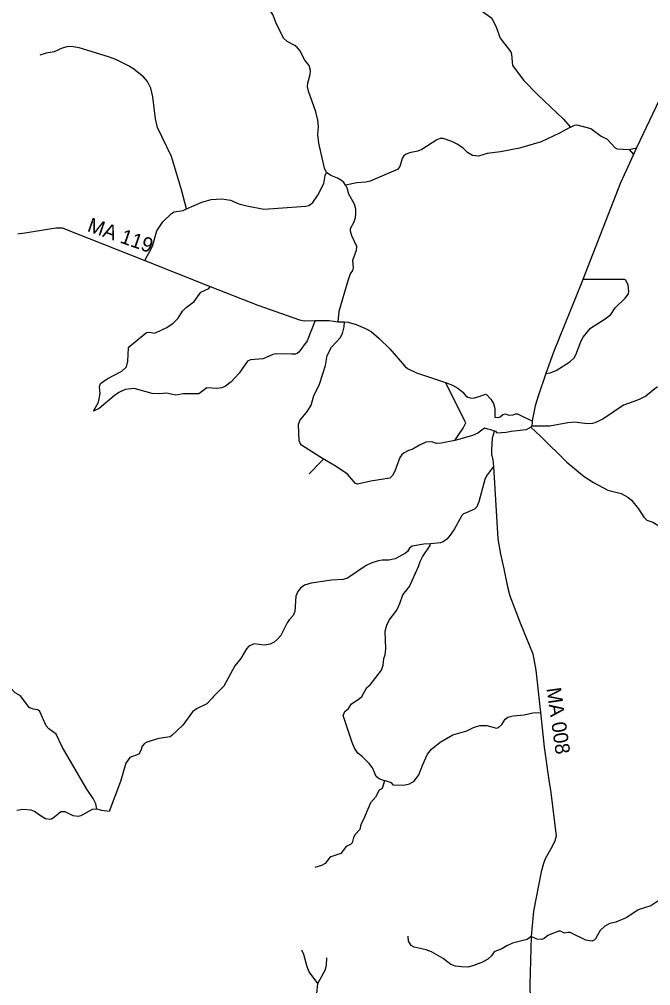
# Model space of a CAD drawing. Extents: x 332 to 501, y 9447 to 9559.
# Drawn here: x 460.06 to 476.49, y 9511.64 to 9536.78 of the extents above; entities that cross this region are included whole.
import ezdxf

# ---------------------------------------------------------------- set-up
doc = ezdxf.new("R2010")
doc.units = 0
for name, color, linetype in [('Level 2', 7, 'Continuous'), ('Level 31', 7, 'Continuous'), ('Level 4', 7, 'Continuous'), ('Level 5', 7, 'Continuous'), ('Level 6', 7, 'Continuous'), ('Level 7', 7, 'Continuous'), ('Level 8', 7, 'Continuous')]:
    doc.layers.add(name, color=color, linetype=linetype)

msp = doc.modelspace()

# ---------------------------------------------------------------- linework, layer by layer
at = {"layer": 'Level 2'}
for points in [[(476.9728, 9535.2227), (476.1217, 9533.4359)], [(476.0422, 9533.261), (475.8954, 9532.9401)], [(476.1217, 9533.4359), (476.0422, 9533.261)], [(475.8954, 9532.9401), (475.7029, 9532.5298), (474.7247, 9530.0083)], [(474.7247, 9530.0083), (474.6986, 9529.941)], [(474.6986, 9529.941), (473.9637, 9528.1206), (473.7625, 9527.5643)], [(473.7625, 9527.5643), (473.5586, 9526.9752), (473.4879, 9526.7279), (473.4094, 9526.3344)], [(473.404, 9526.3076), (473.3946, 9526.2002)], [(473.4094, 9526.3344), (473.404, 9526.3076)]]:
    msp.add_lwpolyline(points, dxfattribs=at)
at = {"layer": 'Level 4'}
for points in [[(460.0993, 9531.2058), (461.0047, 9531.3593), (461.1721, 9531.3548), (463.3279, 9530.5034)], [(463.3279, 9530.5034), (465.022, 9529.8323)], [(465.022, 9529.8323), (466.261, 9529.348), (467.3464, 9528.958), (467.4676, 9528.9403), (467.7569, 9528.9458)], [(467.7569, 9528.9458), (468.1214, 9528.9428), (468.3481, 9528.9107)], [(468.3481, 9528.9107), (468.5226, 9528.9082)], [(468.5226, 9528.9082), (468.6186, 9528.9025), (468.8206, 9528.8368), (469.0655, 9528.7397), (469.2146, 9528.6616), (469.4144, 9528.4872), (469.6996, 9528.2045), (470.0903, 9527.754), (470.1597, 9527.6971), (470.3983, 9527.5873), (471.1483, 9527.3317)], [(471.1483, 9527.3317), (471.3322, 9527.2655), (471.4748, 9527.1822), (471.6023, 9527.0787), (471.6729, 9526.9922), (471.7336, 9526.9525), (471.7891, 9526.931), (471.8711, 9526.9247), (472.0261, 9526.9672)], [(472.0261, 9526.9672), (472.1934, 9527.0257)], [(472.1934, 9527.0257), (472.2287, 9527.0118)], [(472.352, 9525.4304), (472.3861, 9525.318)], [(472.3861, 9525.318), (472.3965, 9525.148)], [(472.3965, 9525.148), (472.5111, 9523.267), (472.5818, 9522.8631), (472.6692, 9522.4887)], [(472.6692, 9522.4887), (472.7634, 9522.0149), (472.8253, 9521.7852), (473.0941, 9521.0785), (473.4223, 9520.2783), (473.498, 9519.8466), (473.627, 9518.7501)], [(473.627, 9518.7501), (473.6355, 9518.6673)], [(473.6355, 9518.6673), (473.7201, 9517.8423), (473.8439, 9516.9871)], [(473.8439, 9516.9871), (473.8941, 9516.6696)], [(473.8941, 9516.6696), (474.0307, 9515.5298)], [(474.0307, 9515.5298), (473.9965, 9515.4101), (473.9258, 9515.2612), (473.7461, 9514.9437), (473.6974, 9514.8233), (473.6419, 9514.6037), (473.4424, 9513.5839), (473.3815, 9512.9204)], [(473.3815, 9512.9204), (473.3415, 9511.6756), (473.3582, 9511.3032)]]:
    msp.add_lwpolyline(points, dxfattribs=at)
at = {"layer": 'Level 5'}
for points in [[(468.057, 9532.7962), (468.0014, 9532.9072), (467.8515, 9533.5612), (467.8286, 9533.7806), (467.8412, 9533.9927), (467.826, 9534.1593), (467.7793, 9534.3738), (467.5837, 9534.914), (467.561, 9535.0201), (467.5686, 9535.1286), (467.6253, 9535.3432), (467.6367, 9535.4492), (467.6026, 9535.5766), (467.4916, 9535.7205), (467.3565, 9535.9654), (467.2971, 9536.0389), (467.2267, 9536.0983), (467.0309, 9536.2039), (466.9324, 9536.2872), (466.7457, 9536.676), (466.6548, 9536.9032), (466.5828, 9537.0091), (466.4591, 9537.1177), (466.2565, 9537.2555)], [(471.9087, 9537.1788), (472.0856, 9536.9993), (472.3506, 9536.8195), (472.4629, 9536.6012), (472.5753, 9536.2907), (472.849, 9535.9297), (472.8693, 9535.8702), (472.8745, 9535.7654)], [(472.8745, 9535.7654), (472.8926, 9535.5787), (473.1914, 9535.1867), (473.5498, 9534.8181), (474.2149, 9534.1933), (474.4022, 9533.9722)], [(464.4074, 9531.8478), (464.2785, 9532.3419), (464.0169, 9533.2102), (463.6521, 9533.9624), (463.5979, 9534.1896), (463.5285, 9534.7626), (463.478, 9534.9923), (463.3909, 9535.1639), (463.2912, 9535.2838), (463.0493, 9535.4752)], [(474.4022, 9533.9722), (474.5055, 9534.0223), (474.5709, 9534.033), (474.9331, 9533.9359), (475.2019, 9533.739), (475.36, 9533.6607), (475.5642, 9533.4323), (475.6172, 9533.4121), (475.9302, 9533.3918)], [(474.4022, 9533.9722), (474.1219, 9533.8173), (473.6419, 9533.5951), (473.079, 9533.4247), (472.5843, 9533.3326), (472.2385, 9533.2909), (472.0087, 9533.2228), (471.8537, 9533.2334), (471.726, 9533.3149), (471.5973, 9533.4386), (471.4496, 9533.5282), (471.3146, 9533.5976), (471.0896, 9533.6755)], [(471.0896, 9533.6755), (471.0079, 9533.6797), (470.9208, 9533.6443), (470.532, 9533.3906), (470.426, 9533.3502), (470.214, 9533.3086), (470.1055, 9533.2594), (470.0625, 9533.224), (470.0221, 9533.1584), (469.9628, 9532.9502), (469.9073, 9532.8832), (469.8606, 9532.8529), (469.1891, 9532.569), (469.0756, 9532.5399), (468.8458, 9532.5236), (468.5462, 9532.4674)], [(475.9302, 9533.3918), (476.1217, 9533.4359)], [(475.9302, 9533.3918), (476.0422, 9533.261)], [(468.5462, 9532.4674), (468.5061, 9532.535), (468.445, 9532.5851), (468.3397, 9532.6485), (468.168, 9532.7191), (468.057, 9532.7962)], [(468.5462, 9532.4674), (468.5807, 9532.4079), (468.6249, 9532.2383), (468.7688, 9531.9795), (468.8079, 9531.8497), (468.8117, 9531.7284), (468.8004, 9531.6148), (468.7651, 9531.5038), (468.6729, 9531.3296), (468.6691, 9531.274), (468.7007, 9531.1579), (468.8308, 9530.8802), (468.8244, 9530.7616), (468.7259, 9530.5092), (468.7474, 9530.3123), (468.7297, 9530.2454), (468.6704, 9530.1558), (468.6063, 9529.9805)], [(464.4074, 9531.8478), (464.8102, 9532.0216), (465.0468, 9532.0944), (465.3321, 9532.1121), (465.5581, 9532.0713)], [(463.3279, 9530.5034), (463.5196, 9530.8777), (463.6345, 9531.2791), (463.7885, 9531.5101), (464.0156, 9531.7275), (464.0844, 9531.7682), (464.3206, 9531.8104), (464.4074, 9531.8478)], [(460.0993, 9531.2058), (460.0141, 9531.1901)], [(467.4051, 9525.705), (467.3552, 9525.7699), (467.3439, 9525.8191), (467.3205, 9526.2416), (467.3616, 9526.3429), (467.5572, 9526.5827), (467.6506, 9526.7455), (467.7225, 9526.9879), (467.874, 9527.2908), (468.0229, 9527.7779), (468.0711, 9528.0327), (468.1869, 9528.2517), (468.4053, 9528.4936), (468.4664, 9528.6046), (468.5149, 9528.7783), (468.5226, 9528.9082)], [(471.6831, 9526.281), (471.1483, 9527.3317)], [(477.8897, 9527.1369), (477.7262, 9527.1166), (477.2171, 9527.2924), (477.1078, 9527.3104), (476.9841, 9527.3009), (476.6382, 9527.2011), (476.3631, 9526.979), (476.1915, 9526.8881), (476.0509, 9526.8401)], [(472.2287, 9527.0118), (472.3309, 9526.8948), (472.3967, 9526.7822), (472.4311, 9526.657), (472.4315, 9526.4275)], [(476.0509, 9526.8401), (475.7856, 9526.7391), (475.2469, 9526.3807), (475.0375, 9526.2859)], [(471.4938, 9525.9767), (471.6143, 9526.1425), (471.6831, 9526.281)], [(475.0375, 9526.2859), (474.9736, 9526.2659), (474.8393, 9526.2581), (474.5176, 9526.298), (474.3349, 9526.2823), (473.8618, 9526.2003), (473.3946, 9526.2002)], [(471.3892, 9525.822), (471.4938, 9525.9767)], [(472.1664, 9526.1485), (471.9961, 9526.0141), (471.8537, 9525.9547), (471.5815, 9525.8734)], [(473.3695, 9526.1693), (473.6341, 9525.9317), (474.3088, 9525.2594), (474.7632, 9524.887), (475.0005, 9524.7269), (475.3786, 9524.5279), (475.7245, 9524.4421), (475.8936, 9524.3538), (475.9887, 9524.2685), (476.1698, 9524.0421), (476.3134, 9523.8273), (476.3928, 9523.754)], [(471.3892, 9525.822), (471.0403, 9525.75), (470.9167, 9525.7438), (470.7916, 9525.786), (470.6351, 9525.7766), (470.474, 9525.7047), (470.2847, 9525.5889), (470.1861, 9525.5654), (470.0719, 9525.5044), (470.0031, 9525.4419), (469.9639, 9525.3793), (469.8328, 9525.029), (469.7672, 9524.9091), (469.7015, 9524.8473), (469.2068, 9524.7665), (468.8584, 9524.6844), (468.8092, 9524.7071), (468.6004, 9524.948), (468.3031, 9525.1498), (468.0116, 9525.3178)], [(471.5815, 9525.8734), (471.3892, 9525.822)], [(467.9785, 9525.3389), (467.4051, 9525.705)], [(467.98, 9525.3379), (467.9785, 9525.3389)], [(468.0112, 9525.3181), (467.98, 9525.3379)], [(468.0116, 9525.3178), (468.0112, 9525.3181)], [(472.3965, 9525.148), (472.2152, 9524.9003), (472.1714, 9524.8128), (472.0175, 9524.2238), (471.9645, 9524.0962), (471.9082, 9524.0353), (471.6896, 9523.9396)], [(471.6896, 9523.9396), (471.6225, 9523.9135), (471.5772, 9523.8721), (471.3852, 9523.527), (471.2742, 9523.3604), (471.1843, 9523.2613), (471.0891, 9523.1879), (471.0204, 9523.1582), (470.7609, 9523.136)], [(476.3928, 9523.754), (476.5508, 9523.6961), (476.6788, 9523.6211), (476.76, 9523.4798), (476.7975, 9523.4501), (476.913, 9523.4329)], [(470.7609, 9523.136), (470.5876, 9523.1294), (470.2847, 9523.0789), (470.2114, 9523.0221), (470.1584, 9522.9363), (470.1105, 9522.8908), (469.8379, 9522.7445), (469.6789, 9522.7078), (469.5047, 9522.7121), (469.4095, 9522.6965), (469.2321, 9522.6384), (469.0882, 9522.5678), (468.6035, 9522.2408), (468.4824, 9522.2093), (468.1794, 9522.1866), (467.6519, 9522.1159), (467.4802, 9522.0629), (467.3779, 9521.9859), (467.3023, 9521.8988), (467.2556, 9521.7726), (467.2265, 9521.3738), (467.1811, 9521.2728), (467.0776, 9521.1605), (467.0246, 9521.0772), (466.863, 9520.7528), (466.7772, 9520.6518), (466.6863, 9520.5761), (466.5866, 9520.5218), (466.4327, 9520.5004), (466.1727, 9520.5307), (466.0325, 9520.4751), (465.9694, 9520.407), (465.8255, 9520.1495), (465.6665, 9519.9589), (465.3775, 9519.4339), (465.1067, 9519.1575)], [(465.0823, 9519.1274), (464.9376, 9518.9699), (464.683, 9518.8543), (464.5628, 9518.7645), (464.316, 9518.4166), (464.0308, 9518.1465), (463.9803, 9518.1165), (463.6907, 9518.0735), (463.3732, 9517.9786), (463.3177, 9517.9446), (463.2533, 9517.8739), (463.2214, 9517.7583), (463.1652, 9517.6661), (462.9307, 9517.5767), (462.8333, 9517.4283), (462.6904, 9516.9538), (462.3961, 9516.1693)], [(465.1067, 9519.1575), (465.0823, 9519.1274)], [(469.7967, 9516.861), (470.1004, 9516.8629), (470.2115, 9516.8894), (470.3377, 9516.9626), (470.4575, 9517.128), (470.561, 9517.3981), (470.686, 9517.6657), (470.7877, 9517.7949), (471.0078, 9517.973), (471.3373, 9518.1641), (471.7033, 9518.274), (471.8762, 9518.3548), (472.0419, 9518.4095), (472.2233, 9518.4078), (472.4742, 9518.3443), (472.5319, 9518.3584), (472.6194, 9518.4349), (472.7042, 9518.5756), (472.7761, 9518.6249), (472.9124, 9518.6627), (473.1977, 9518.6867), (473.4274, 9518.7385), (473.627, 9518.7501)], [(462.0755, 9516.2344), (461.9495, 9516.2248), (461.6575, 9516.0608), (461.5873, 9516.0421), (461.4546, 9516.0632), (461.2516, 9516.1616), (461.1376, 9516.1639), (460.983, 9516.0327), (460.8971, 9515.9718), (460.8518, 9515.9609), (460.7347, 9515.9843), (460.5801, 9516.0741), (460.4521, 9516.1756), (460.3631, 9516.2037), (460.1507, 9516.2216), (459.9962, 9516.1951)], [(462.3961, 9516.1693), (462.2088, 9516.1959), (462.0755, 9516.2344)]]:
    msp.add_lwpolyline(points, dxfattribs=at)
at = {"layer": 'Level 6'}
for points in [[(463.0493, 9535.4752), (462.9339, 9535.5503), (462.5702, 9535.731), (462.3806, 9535.8044), (461.617, 9536.0359), (461.456, 9536.0644), (461.3249, 9536.0689), (461.176, 9536.0273), (460.9636, 9535.9301), (460.7551, 9535.8973), (460.5933, 9535.8499)], [(465.5581, 9532.0713), (465.7688, 9531.9821), (465.9758, 9531.924), (466.4175, 9531.8433), (467.5143, 9531.9177), (467.5963, 9531.9367), (467.6935, 9532.0123), (467.826, 9532.208), (467.9838, 9532.5096), (468.0141, 9532.7179), (468.057, 9532.7962)], [(473.7625, 9527.5643), (473.8719, 9527.5842), (474.0341, 9527.6406), (474.3902, 9527.8662), (474.4995, 9527.9755), (474.5453, 9528.0496), (474.6794, 9528.4155), (474.7342, 9528.5103), (474.9285, 9528.7422), (475.303, 9528.9859), (475.4534, 9529.105), (475.5646, 9529.2719), (475.8294, 9529.5273), (475.914, 9529.6393), (475.925, 9529.6989), (475.9046, 9529.8681), (475.8451, 9529.9958), (475.8122, 9530.0099), (474.7247, 9530.0083)], [(461.9878, 9526.5843), (462.1162, 9526.8187), (462.1579, 9527.0421), (462.142, 9527.2199), (462.1658, 9527.3053), (462.3415, 9527.4235), (462.7285, 9527.6262), (462.8437, 9527.7434), (462.8804, 9527.8904), (462.8953, 9528.234), (462.93, 9528.2797), (463.3657, 9528.6343), (463.456, 9528.6423), (463.5711, 9528.6185), (463.6158, 9528.6294), (463.8967, 9528.7616), (464.0605, 9528.8728), (464.1925, 9529.0089), (464.3076, 9529.1837), (464.4019, 9529.2869), (464.6038, 9529.4376), (464.7835, 9529.6792), (464.9859, 9529.7736), (465.022, 9529.8323)], [(468.6063, 9529.9805), (468.37, 9529.1751), (468.3481, 9528.9107)], [(467.7569, 9528.9458), (467.548, 9528.4165), (467.331, 9528.1234), (467.2881, 9528.0896), (467.2474, 9528.0715), (467.1536, 9528.0681), (466.722, 9528.0737), (466.652, 9528.0613), (466.4, 9527.9478), (466.0757, 9527.9241), (466, 9527.8914), (465.7763, 9527.5723), (465.573, 9527.3536), (465.4272, 9527.2373), (465.3289, 9527.1972), (465.1978, 9527.1791), (464.9413, 9527.1949), (464.7334, 9527.0362), (464.329, 9527.0396), (464.1346, 9526.9989), (463.8883, 9527.052), (463.712, 9527.0339), (463.5154, 9527.0463), (463.0454, 9527.1785), (462.8081, 9527.1491), (462.6499, 9527.0689), (462.5256, 9526.9831), (462.1392, 9526.6589), (461.9878, 9526.5843)], [(467.5974, 9524.9525), (467.9351, 9525.2948)], [(467.9351, 9525.2948), (467.9785, 9525.3389)], [(468.5168, 9518.5884), (468.49, 9518.6737), (468.529, 9518.7713), (468.6224, 9518.852), (468.7057, 9518.977), (468.9064, 9519.1045), (468.9733, 9519.1688), (469.102, 9519.3973), (469.1878, 9519.4692), (469.4807, 9519.8517), (469.5281, 9519.9764), (469.5469, 9520.1542), (469.5816, 9520.2505), (469.5981, 9520.407), (469.5804, 9520.8651), (469.6195, 9521.0179), (469.6826, 9521.1504), (469.8795, 9521.4104), (469.9641, 9521.5858), (470.0436, 9521.8117), (470.2114, 9522.0263), (470.4515, 9522.543), (470.4902, 9522.6721), (470.5527, 9522.7943), (470.7511, 9523.0953), (470.7609, 9523.136)], [(462.0755, 9516.2344), (462.0443, 9516.3728), (461.981, 9516.5128), (461.8161, 9516.7499), (461.1838, 9517.8407), (461.0189, 9518.1874), (460.8246, 9518.3251), (460.7569, 9518.3997), (460.5875, 9518.7712), (460.5423, 9518.8141), (460.4158, 9518.8322), (460.3089, 9518.8786), (460.0838, 9519.1788), (459.9505, 9519.2601), (459.8285, 9519.3877)], [(469.4196, 9517.0246), (469.3466, 9517.0814), (469.2483, 9517.3109), (469.1659, 9517.4201), (468.9823, 9517.6069), (468.8711, 9517.6943), (468.7818, 9517.8165), (468.7203, 9517.9645), (468.5168, 9518.5884)], [(469.5641, 9516.9723), (469.4982, 9516.7735), (469.4248, 9516.7261), (469.3277, 9516.5499)], [(469.5641, 9516.9723), (469.4196, 9517.0246)], [(469.588, 9516.9666), (469.5641, 9516.9723)], [(469.7967, 9516.861), (469.7405, 9516.9175), (469.588, 9516.9666)], [(469.3277, 9516.5499), (469.1978, 9516.4002), (469.0193, 9515.9684), (468.9426, 9515.8368), (468.9177, 9515.7081), (468.7958, 9515.572), (468.7574, 9515.4941), (468.719, 9515.3564), (468.675, 9515.3163)], [(478.0067, 9514.3532), (477.9234, 9514.338), (477.713, 9514.2318), (477.5234, 9514.1653), (477.3706, 9514.1584), (477.1612, 9514.0543), (476.9071, 9514.0405), (476.8555, 9514.0216), (476.6798, 9513.845), (476.4992, 9513.715), (476.1627, 9513.6178), (475.8699, 9513.4193), (475.5821, 9513.2963), (475.4253, 9513.2626), (475.2973, 9513.1932), (475.1732, 9513.0811), (475.0561, 9512.8598), (475.0194, 9512.8231), (474.9646, 9512.7992)], [(470.256, 9512.6865), (470.1848, 9512.7993), (470.1759, 9512.9271)], [(473.3815, 9512.9204), (473.2785, 9512.8406), (472.8933, 9512.7463), (472.7494, 9512.6798), (472.6194, 9512.5965), (472.4745, 9512.5489), (472.4199, 9512.5212), (472.3435, 9512.4189), (472.2542, 9512.3336), (472.1093, 9512.2503), (471.889, 9512.164), (471.7332, 9512.1253), (471.5704, 9512.1323), (471.4106, 9512.1502), (471.2895, 9512.191)], [(474.9646, 9512.7992), (474.799, 9512.8292), (474.3921, 9513.0219), (474.3465, 9513.0279), (474.2463, 9513.0081), (474.14, 9513.0588), (474.0944, 9513.0578), (473.8175, 9512.9447), (473.7152, 9512.8663), (473.6617, 9512.8445), (473.5246, 9512.8564), (473.3815, 9512.9204)], [(471.2895, 9512.191), (471.0899, 9512.3483), (470.7892, 9512.5261), (470.6483, 9512.5768), (470.3327, 9512.6463), (470.256, 9512.6865)], [(467.7792, 9511.1807), (467.8298, 9511.6962)]]:
    msp.add_lwpolyline(points, dxfattribs=at)
at = {"layer": 'Level 7'}
for points in [[(468.675, 9515.3163), (468.5668, 9515.2647), (468.4219, 9515.0819), (468.1668, 9514.9915), (468.1281, 9514.9637), (468.0219, 9514.8226), (467.9187, 9514.768), (467.747, 9514.7134)], [(467.8298, 9511.6962), (467.6015, 9512.0002), (467.5459, 9512.1342), (467.4584, 9512.4571), (467.412, 9512.5636)], [(467.8298, 9511.6962), (468.0243, 9512.0647), (468.0501, 9512.1729), (468.061, 9512.3645)]]:
    msp.add_lwpolyline(points, dxfattribs=at)
at = {"layer": 'Level 8'}
for points in [[(472.5198, 9526.4185), (472.5774, 9526.4397), (472.6436, 9526.5032), (472.7054, 9526.5145), (472.7961, 9526.4796), (472.913, 9526.4943)], [(472.913, 9526.4943), (472.968, 9526.5183), (473.0272, 9526.5157), (473.1793, 9526.4378)], [(472.4315, 9526.4275), (472.5198, 9526.4185)], [(473.1793, 9526.4378), (473.4094, 9526.3344)], [(472.2517, 9526.1219), (472.1664, 9526.1485)], [(472.3321, 9526.0968), (472.2517, 9526.1219)], [(472.4252, 9526.0677), (472.3321, 9526.0968)], [(472.3747, 9525.8923), (472.4252, 9526.0677)], [(472.4871, 9526.0159), (472.4656, 9526.0551), (472.4252, 9526.0677)], [(472.7277, 9526.0357), (472.4871, 9526.0159)], [(472.8635, 9526.0562), (472.7277, 9526.0357)], [(473.3695, 9526.1693), (473.2468, 9526.1005), (472.8635, 9526.0562)], [(473.3946, 9526.2002), (473.3695, 9526.1693)], [(472.359, 9525.5732), (472.3747, 9525.8923)], [(472.352, 9525.4304), (472.359, 9525.5732)]]:
    msp.add_lwpolyline(points, dxfattribs=at)

# ---------------------------------------------------------------- texts
at = {"layer": 'Level 31'}
for s, rotation, p in [('MA 119', 340.72471, (461.8029, 9531.2745)), ('MA 008', 278.1301, (473.7768, 9519.3743))]:
    msp.add_text(s, height=0.38, rotation=rotation, dxfattribs=at).set_placement(p)

doc.saveas('drawing.dxf')
